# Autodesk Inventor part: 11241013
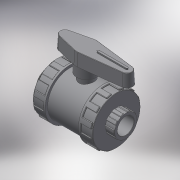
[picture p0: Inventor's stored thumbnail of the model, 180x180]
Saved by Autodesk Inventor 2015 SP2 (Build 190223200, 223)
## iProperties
Created: 2017-11
Part Number: 11241013
Material: Generic
Description: PLASSON BI STOP VALVE THR PVC 1.1/4"
Document SubType Name: Modeling
Designer: KIM
Density: 1 g/cm^3
Appearance: Default
Author: KIM
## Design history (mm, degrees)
derived "112410 - 112710.ipt"
feature "Solid1::112410 - 112710.ipt"
tag "TaggingFeature1"
body "Solid1"
other parameters: "d1" = 38.952, "d3" = 22, "d4" = 31.1616, "d5" = 15.4, "d7" = 54.5328, "d8" = 72, "d13" = 1.16856, "d23" = 22, "d24" = 76.8, "d25" = 0.77904, "d26" = 1.16856, "d27" = 12, "d28" = 6, "d29" = 16.5, "d30" = 0, "d35" = 1.16856, "d45" = 360 deg, "d47" = 0.77904, "d50" = 44, "d51" = 24, "d53" = 0, "d55" = 7.7904, "d56" = 3.8952, "d57" = 15.4, "d58" = 0, "d59" = 1.16856, "d61" = 360 deg, "d63" = 32, "d64" = 74, "d66" = 96, "d68" = 16, "d69" = 28.8, "d70" = 18.5, "d71" = 3 deg, "d73" = 1.6, "d74" = 38.4, "d75" = 2.22, "d76" = 0, "d77" = 0.77904, "G_" = 38.952, "l_" = 22, "F_" = 74, "J_" = 96, "d67" = 32, "d72" = 8
